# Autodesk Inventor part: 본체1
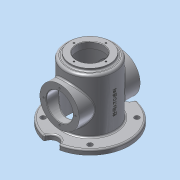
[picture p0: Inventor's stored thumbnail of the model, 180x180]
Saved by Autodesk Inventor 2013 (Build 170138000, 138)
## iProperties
Created: 2018-04
Part Number: 본체1
Material: 알루미늄 6061
Document SubType Name: Modeling
Designer: dgall
Density: 2.71 g/cm^3
Mass: 1154.51 g
Surface Area: 1206.36 cm^2
Volume: 426.017 cm^3
Author: dgall
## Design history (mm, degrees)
sketch "스케치1"
  geometry: C1 r 50 at (0, 0); 1 further point
  constraints: 1 centre point, 1 coincident
  dimensions: "d0" = 100 diameter of C1
extrude "돌출1" new body sketch "스케치1" distance "d2" = 8; taper "d3" = 0 deg
sketch "스케치2"
  geometry: C1 r 50 at (0, 0) reference; C2 r 80 at (0, 0)
  constraints: 1 centre point, 1 coincident
  dimensions: "d4" = 160 diameter of C2
extrude "돌출2" join sketch "스케치2" distance "d6" = 10; taper "d7" = 0 deg
node "작업 평면1"
sketch "스케치18"
  geometry: L1 (-80, 0)-(80, 0); L2 (0, -80)-(0, 80); L3 (0, 0)-(-56.569, 56.569); L4 (0, 0)-(56.569, 56.569); L5 (0, 0)-(-56.569, -56.569); L6 (0, 0)-(56.569, -56.569); C1 r 15 at (0, -80); C2 r 15 at (0, 80); C3 r 5 at (-47.73, 47.73); C4 r 5 at (47.73, 47.73); C5 r 5 at (47.73, -47.73); C6 r 5 at (-47.73, -47.73); A1 r 67.5 centre (0, 0) between (-47.73, 47.73) and (47.73, 47.73); 1 further point
  constraints: 12 end point, 7 centre point, 4 point on circle, 4 point on line, 3 coincident, 3 midpoint, 3 perpendicular, 1 collinear, 1 horizontal, 9 other
  dimensions: "d91" = 30 diameter of C2; "d93" = 30 diameter of C1; "d94" = 45 deg angle of L1 L3; "d95" = 135 diameter of A1; "d96" = 10 diameter of C3; "d97" = 10 diameter of C4; "d98" = 10 diameter of C5; "d99" = 10 diameter of C6
extrude "돌출10" cut sketch "스케치18" distance "d100" = 10; taper "d101" = 0 deg
fillet "모깎기9" dims "d102" = 3
fillet "모깎기10" dims "d103" = 3
sketch "스케치19"
  geometry: C1 r 50 at (0, 0); A1 r 77 centre (0, 0) between (17.301, -75.031) and (17.301, 75.031) reference
  constraints: 1 centre point, 1 coincident
  dimensions: "d104" = 100 diameter of C1
extrude "돌출11" join sketch "스케치19" distance "d106" = 110; taper "d107" = 0 deg
sketch "스케치20"
  geometry: C1 r 50 at (0, 0) reference; C2 r 40 at (0, 0)
  constraints: 1 centre point, 1 coincident
  dimensions: "d108" = 80 diameter of C2
extrude "돌출12" join sketch "스케치20" distance "d110" = 5; taper "d111" = 0 deg
sketch "스케치22"
  geometry: C1 r 50 at (0, 0) reference; C2 r 45 at (0, 0)
  constraints: 1 centre point, 1 coincident
  dimensions: "d112" = 90 diameter of C2
extrude "돌출13" cut sketch "스케치22" distance "d114" = 120; taper "d115" = 0 deg
sketch "스케치23"
  geometry: C1 r 45 at (0, 0) reference; C2 r 27 at (0, 0)
  constraints: 1 centre point, 1 coincident
  dimensions: "d116" = 54 diameter of C2
extrude "돌출14" cut sketch "스케치23" distance "d118" = 13; taper "d119" = 0 deg
node "작업 평면2"
sketch "스케치24"
  geometry: L1 (-62.446, 68)-(69.019, 68); L2 (-80, 8)-(-17.975, 8) reference; L3 (0, 132.874)-(0, 0); C1 r 40 at (0, 68)
  constraints: 4 end point, 2 point on line, 1 centre point, 1 horizontal, 1 perpendicular
  dimensions: "d121" = 60 distance between parallel lines of L2 L1; "d122" = 80 diameter of C1
extrude "돌출15" join sketch "스케치24" stored distance "d123" = 13; taper "d124" = 0 deg
sketch "스케치25"
  geometry: C1 r 40 at (0, 0) reference; C2 r 27 at (0, 0); 1 further point
  constraints: 1 centre point, 1 coincident
  dimensions: "d125" = 54 diameter of C2
extrude "돌출16" cut sketch "스케치25" stored distance "d127" = 13; taper "d128" = 0 deg
sketch "스케치26" dims "d129" = 65
  geometry: L1 (0, 0)-(0, 32.5); C1 r 27 at (0, 0) reference; C2 r 40 at (0, 0) reference; C3 r 2 at (0, 32.5); C4 r 2 at (-32.5, 0); C5 r 2 at (0, -32.5); C6 r 2 at (32.5, 0); 1 further point
  constraints: 4 centre point, 2 coincident, 2 end point, 1 vertical, 1 vertical alignment, 11 other
  dimensions: "d131" = 4 diameter of C3; "d134" = 360 deg dimension on C1.centre C3.centre (derived)
hole "구멍3" sketch "스케치26" at (0, 32.5), (-32.5, 0), (0, -32.5), (32.5, 0) diameter "d136" = 3.242; stored, may be unused: countersink angle "d140" = 90 deg, drill point angle "d142" = 118 deg; dims "d137" = 8, "d138" = 4, "d139" = 2, "d141" = 10
sketch "스케치27" dims "d143" = 65
  geometry: L1 (0, 0)-(0, 32.5); C1 r 27 at (0, 0) reference; C2 r 40 at (0, 0) reference; C3 r 2 at (0, 32.5); C4 r 2 at (-32.5, 0); C5 r 2 at (0, -32.5); C6 r 2 at (32.5, 0)
  constraints: 4 centre point, 2 coincident, 2 end point, 1 vertical, 1 vertical alignment, 11 other
  dimensions: "d145" = 4 diameter of C3; "d148" = 360 deg dimension on C1.centre C3.centre (derived)
hole "구멍4" sketch "스케치27" at (-32.5, 0), (0, -32.5), (32.5, 0), (0, 32.5) diameter "d150" = 3.242; stored, may be unused: countersink angle "d154" = 90 deg, drill point angle "d156" = 118 deg; dims "d151" = 8, "d152" = 4, "d153" = 2, "d155" = 10
chamfer "모따기4" distance "d158" = 1; stored, may be unused: second distance "d159" = 2, angle "d160" = 45 deg
chamfer "모따기5" distance "d161" = 1; stored, may be unused: second distance "d162" = 2, angle "d163" = 45 deg
chamfer "모따기6" distance "d164" = 1; stored, may be unused: second distance "d165" = 2, angle "d166" = 45 deg
node "작업 평면3"
sketch "스케치28"
  geometry: L1 (-21.818, 27.113)-(-21.818, 76.887); L2 (-21.818, 76.887)-(21.818, 76.887); L3 (21.818, 76.887)-(21.818, 27.113); L4 (21.818, 27.113)-(-21.818, 27.113); L5 (-21.818, 52)-(21.818, 52); L6 (0, 76.887)-(0, 27.113); 1 further point
  constraints: 4 end point, 4 midpoint, 1 point on line, 2 other
  dimensions: "d167" = 70 distance from line of point (0, -18) L5
extrude "돌출17" join sketch "스케치28" distance "d168" = 0.5; taper "d169" = 0 deg
fillet "모깎기12" dims "d170" = 3
fillet "모깎기13" dims "d171" = 3
fillet "모깎기14" dims "d172" = 5
fillet "모깎기15" dims "d173" = 3
chamfer "모따기7" distance "d174" = 1; stored, may be unused: second distance "d175" = 2, angle "d176" = 45 deg
node "솔리드1"
mirror "대칭3"
mirror "대칭4"
other parameters: "d37" = -62, "d120" = -62
